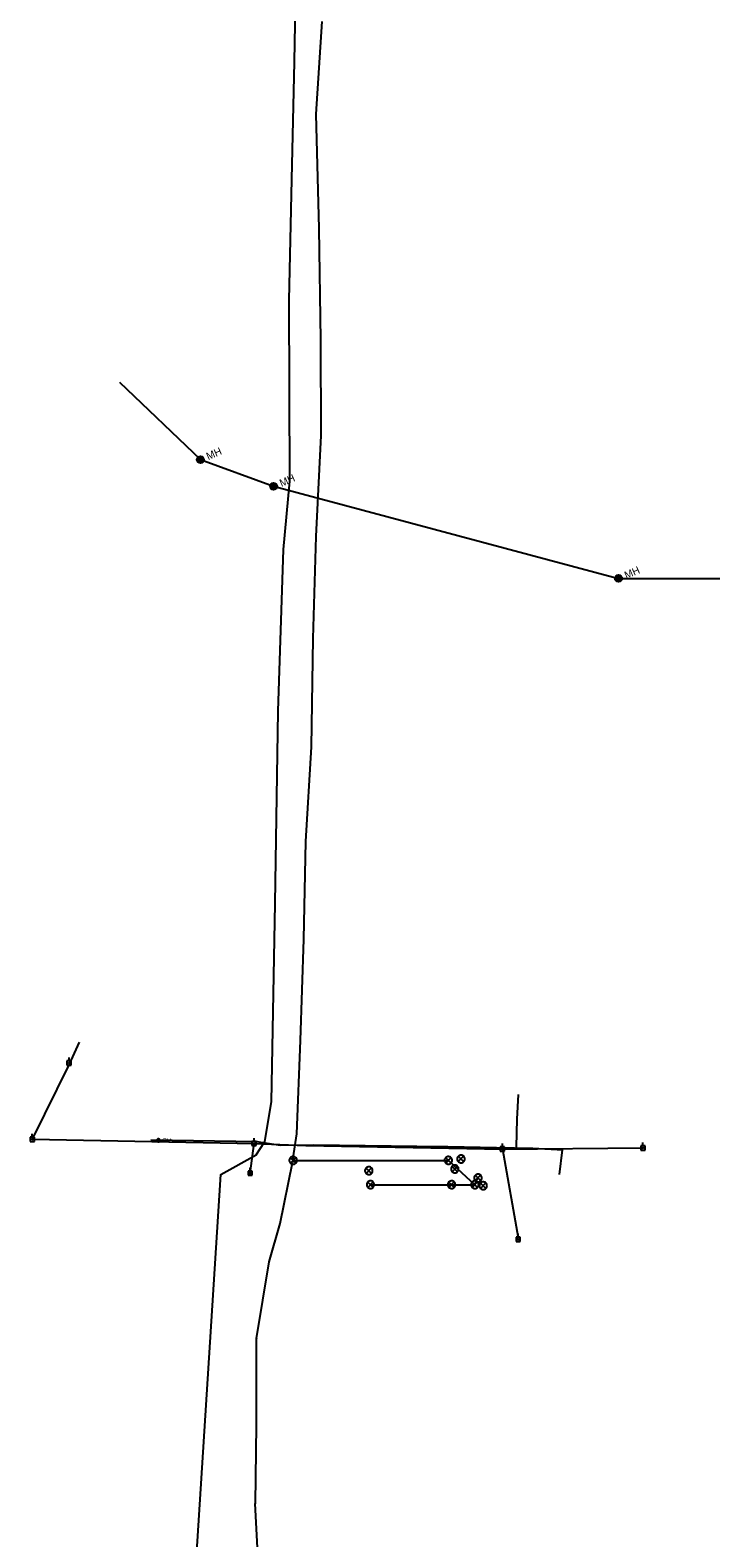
# Model space of a CAD drawing. Extents: x 600849 to 606371, y 330010 to 403088.
# Drawn here: x 603935 to 604530, y 341634 to 342935 of the extents above; entities that cross this region are included whole.
import ezdxf

# ---------------------------------------------------------------- set-up
doc = ezdxf.new("R2010")
doc.units = 0
for name, color, linetype in [('E_FTMS', 7, 'Continuous'), ('E_FTMS_Conduit', 7, 'Continuous'), ('E_UTL_EPowerPole', 7, 'Continuous'), ('E_UTL_FO_UG_QWEST', 7, 'Continuous'), ('E_UTL_G', 7, 'Continuous'), ('E_UTL_G_UG', 7, 'Continuous'), ('E_UTL_Overhead', 7, 'Continuous'), ('E_UTL_SAN_MH', 7, 'Continuous'), ('E_UTL_SAN_UG', 7, 'Continuous')]:
    doc.layers.add(name, color=color, linetype=linetype)

msp = doc.modelspace()

# ---------------------------------------------------------------- linework, layer by layer
at = {"layer": 'E_FTMS'}
for points in [[(604165.1, 341959.5), (604165.1, 341960.2), (604164.9, 341960.8), (604164.6, 341961.3), (604164.2, 341961.8), (604163.7, 341962.2), (604163.2, 341962.5), (604162.6, 341962.7), (604162, 341962.8), (604161.3, 341962.8), (604160.7, 341962.7), (604160.2, 341962.4), (604159.7, 341962), (604159.2, 341961.6), (604158.9, 341961), (604158.6, 341960.5), (604158.5, 341959.8), (604158.5, 341959.2), (604158.6, 341958.6), (604158.9, 341958), (604159.2, 341957.5), (604159.7, 341957), (604160.2, 341956.7), (604160.7, 341956.4), (604161.3, 341956.3), (604162, 341956.2), (604162.6, 341956.3), (604163.2, 341956.5), (604163.7, 341956.8), (604164.2, 341957.3), (604164.6, 341957.8), (604164.9, 341958.3), (604165.1, 341958.9), (604165.1, 341959.5)], [(604164.1, 341961.9), (604159.5, 341957.2)], [(604159.5, 341961.8), (604164.1, 341957.2)], [(604299.1, 341959.5), (604299, 341960.2), (604298.9, 341960.8), (604298.6, 341961.3), (604298.2, 341961.8), (604297.7, 341962.2), (604297.2, 341962.5), (604296.6, 341962.7), (604296, 341962.8), (604295.3, 341962.8), (604294.7, 341962.7), (604294.2, 341962.4), (604293.6, 341962), (604293.2, 341961.6), (604292.9, 341961), (604292.6, 341960.5), (604292.5, 341959.8), (604292.5, 341959.2), (604292.6, 341958.6), (604292.9, 341958), (604293.2, 341957.5), (604293.6, 341957), (604294.2, 341956.7), (604294.7, 341956.4), (604295.3, 341956.3), (604296, 341956.2), (604296.6, 341956.3), (604297.2, 341956.5), (604297.7, 341956.8), (604298.2, 341957.3), (604298.6, 341957.8), (604298.9, 341958.3), (604299, 341958.9), (604299.1, 341959.5)], [(604298.1, 341961.9), (604293.5, 341957.2)], [(604293.5, 341961.8), (604298.1, 341957.2)], [(604304.6, 341952), (604304.6, 341952.7), (604304.4, 341953.3), (604304.1, 341953.8), (604303.7, 341954.3), (604303.3, 341954.7), (604302.7, 341955), (604302.1, 341955.3), (604301.5, 341955.3), (604300.9, 341955.3), (604300.3, 341955.2), (604299.7, 341954.9), (604299.2, 341954.5), (604298.8, 341954.1), (604298.4, 341953.6), (604298.2, 341953), (604298.1, 341952.4), (604298.1, 341951.7), (604298.2, 341951.1), (604298.4, 341950.5), (604298.8, 341950), (604299.2, 341949.6), (604299.7, 341949.2), (604300.3, 341948.9), (604300.9, 341948.8), (604301.5, 341948.8), (604302.1, 341948.8), (604302.7, 341949), (604303.3, 341949.4), (604303.7, 341949.8), (604304.1, 341950.3), (604304.4, 341950.8), (604304.6, 341951.4), (604304.6, 341952)], [(604310, 341960.7), (604309.9, 341961.3), (604309.7, 341961.9), (604309.5, 341962.5), (604309.1, 341963), (604308.6, 341963.4), (604308, 341963.7), (604307.5, 341963.9), (604306.8, 341964), (604306.2, 341964), (604305.6, 341963.8), (604305, 341963.6), (604304.5, 341963.2), (604304.1, 341962.7), (604303.7, 341962.2), (604303.5, 341961.6), (604303.4, 341961), (604303.4, 341960.4), (604303.5, 341959.8), (604303.7, 341959.2), (604304.1, 341958.7), (604304.5, 341958.2), (604305, 341957.9), (604305.6, 341957.6), (604306.2, 341957.4), (604306.8, 341957.4), (604307.5, 341957.5), (604308, 341957.7), (604308.6, 341958), (604309.1, 341958.4), (604309.5, 341958.9), (604309.7, 341959.5), (604309.9, 341960.1), (604310, 341960.7)], [(604308.9, 341963), (604304.3, 341958.4)], [(604304.3, 341963), (604309, 341958.3)], [(604230.4, 341950.6), (604230.4, 341951.2), (604230.2, 341951.8), (604229.9, 341952.4), (604229.5, 341952.9), (604229, 341953.3), (604228.5, 341953.6), (604227.9, 341953.8), (604227.3, 341953.9), (604226.6, 341953.9), (604226, 341953.7), (604225.5, 341953.5), (604225, 341953.1), (604224.5, 341952.7), (604224.2, 341952.1), (604223.9, 341951.6), (604223.8, 341950.9), (604223.8, 341950.3), (604223.9, 341949.7), (604224.2, 341949.1), (604224.5, 341948.6), (604225, 341948.1), (604225.5, 341947.8), (604226, 341947.5), (604226.6, 341947.4), (604227.3, 341947.3), (604227.9, 341947.4), (604228.5, 341947.6), (604229, 341947.9), (604229.5, 341948.3), (604229.9, 341948.8), (604230.2, 341949.4), (604230.4, 341950), (604230.4, 341950.6)], [(604229.4, 341953), (604224.8, 341948.3)], [(604224.8, 341952.9), (604229.4, 341948.3)], [(604303.6, 341954.4), (604299, 341949.7)], [(604299, 341954.3), (604303.7, 341949.7)], [(604324.6, 341944.3), (604324.6, 341944.9), (604324.4, 341945.5), (604324.1, 341946.1), (604323.7, 341946.6), (604323.3, 341947), (604322.7, 341947.3), (604322.1, 341947.5), (604321.5, 341947.6), (604320.9, 341947.6), (604320.3, 341947.4), (604319.7, 341947.2), (604319.2, 341946.8), (604318.8, 341946.3), (604318.4, 341945.8), (604318.2, 341945.2), (604318.1, 341944.6), (604318.1, 341944), (604318.2, 341943.4), (604318.4, 341942.8), (604318.8, 341942.3), (604319.2, 341941.8), (604319.7, 341941.4), (604320.3, 341941.2), (604320.9, 341941), (604321.5, 341941), (604322.1, 341941.1), (604322.7, 341941.3), (604323.3, 341941.6), (604323.7, 341942), (604324.1, 341942.5), (604324.4, 341943.1), (604324.6, 341943.7), (604324.6, 341944.3)], [(604323.6, 341946.6), (604319, 341942)], [(604319, 341946.6), (604323.7, 341941.9)], [(604231.9, 341938.5), (604231.8, 341939.2), (604231.6, 341939.8), (604231.3, 341940.3), (604231, 341940.8), (604230.5, 341941.2), (604229.9, 341941.5), (604229.3, 341941.7), (604228.7, 341941.8), (604228.1, 341941.8), (604227.5, 341941.6), (604226.9, 341941.4), (604226.4, 341941), (604226, 341940.6), (604225.6, 341940), (604225.4, 341939.5), (604225.3, 341938.8), (604225.3, 341938.2), (604225.4, 341937.6), (604225.6, 341937), (604226, 341936.5), (604226.4, 341936), (604226.9, 341935.7), (604227.5, 341935.4), (604228.1, 341935.3), (604228.7, 341935.2), (604229.3, 341935.3), (604229.9, 341935.5), (604230.5, 341935.8), (604231, 341936.3), (604231.3, 341936.7), (604231.6, 341937.3), (604231.8, 341937.9), (604231.9, 341938.5)], [(604230.8, 341940.9), (604226.2, 341936.2)], [(604226.2, 341940.8), (604230.9, 341936.2)], [(604301.9, 341938.5), (604301.8, 341939.2), (604301.6, 341939.8), (604301.4, 341940.3), (604301, 341940.8), (604300.5, 341941.2), (604300, 341941.5), (604299.4, 341941.7), (604298.7, 341941.8), (604298.1, 341941.8), (604297.5, 341941.6), (604296.9, 341941.4), (604296.4, 341941), (604296, 341940.6), (604295.7, 341940), (604295.4, 341939.5), (604295.3, 341938.8), (604295.3, 341938.2), (604295.4, 341937.6), (604295.7, 341937), (604296, 341936.5), (604296.4, 341936), (604296.9, 341935.7), (604297.5, 341935.4), (604298.1, 341935.3), (604298.7, 341935.2), (604299.4, 341935.3), (604300, 341935.5), (604300.5, 341935.8), (604301, 341936.3), (604301.4, 341936.7), (604301.6, 341937.3), (604301.8, 341937.9), (604301.9, 341938.5)], [(604300.8, 341940.9), (604296.2, 341936.2)], [(604296.2, 341940.8), (604300.9, 341936.2)], [(604322, 341938.5), (604321.9, 341939.2), (604321.8, 341939.8), (604321.5, 341940.3), (604321.1, 341940.8), (604320.6, 341941.2), (604320.1, 341941.5), (604319.5, 341941.7), (604318.9, 341941.8), (604318.2, 341941.8), (604317.6, 341941.6), (604317.1, 341941.4), (604316.5, 341941), (604316.1, 341940.6), (604315.8, 341940), (604315.5, 341939.5), (604315.4, 341938.8), (604315.4, 341938.2), (604315.5, 341937.6), (604315.8, 341937), (604316.1, 341936.5), (604316.5, 341936), (604317.1, 341935.7), (604317.6, 341935.4), (604318.2, 341935.3), (604318.9, 341935.2), (604319.5, 341935.3), (604320.1, 341935.5), (604320.6, 341935.8), (604321.1, 341936.3), (604321.5, 341936.7), (604321.8, 341937.3), (604321.9, 341937.9), (604322, 341938.5)], [(604321, 341940.9), (604316.4, 341936.2)], [(604316.4, 341940.8), (604321, 341936.2)], [(604329.2, 341937.6), (604329.1, 341938.3), (604329, 341938.9), (604328.7, 341939.4), (604328.3, 341939.9), (604327.8, 341940.3), (604327.3, 341940.6), (604326.7, 341940.8), (604326.1, 341940.9), (604325.4, 341940.9), (604324.8, 341940.8), (604324.3, 341940.5), (604323.7, 341940.1), (604323.3, 341939.7), (604323, 341939.2), (604322.7, 341938.6), (604322.6, 341938), (604322.6, 341937.3), (604322.7, 341936.7), (604323, 341936.1), (604323.3, 341935.6), (604323.7, 341935.1), (604324.3, 341934.8), (604324.8, 341934.5), (604325.4, 341934.4), (604326.1, 341934.3), (604326.7, 341934.4), (604327.3, 341934.6), (604327.8, 341935), (604328.3, 341935.4), (604328.7, 341935.9), (604329, 341936.4), (604329.1, 341937), (604329.2, 341937.6)], [(604328.2, 341940), (604323.6, 341935.3)], [(604323.6, 341939.9), (604328.2, 341935.3)]]:
    msp.add_lwpolyline(points, dxfattribs=at)
at = {"layer": 'E_FTMS_Conduit'}
for points in [[(604131.7, 341614.1), (604129.2, 341663.2), (604129.3, 341663.2), (604130.1, 341731), (604130.3, 341805.8), (604130.3, 341805.9), (604130.3, 341805.8), (604130.3, 341805.8), (604141.1, 341871.9), (604150.5, 341905), (604161.4, 341957.5), (604161.8, 341959.5), (604161.9, 341961.6), (604164.9, 341982.3), (604168.1, 342063.1), (604171.1, 342150.5), (604172.7, 342234.8), (604177.7, 342316.6), (604179.2, 342410), (604181.8, 342498), (604185.9, 342585.2), (604185.8, 342667.9), (604184.3, 342763.9), (604181.6, 342862.8), (604187, 342942.7)], [(604161.8, 341959.5), (604295.8, 341959.5), (604318.7, 341938.5)], [(604228.6, 341938.5), (604298.6, 341938.5), (604318.7, 341938.5), (604321.3, 341944.3)]]:
    msp.add_lwpolyline(points, dxfattribs=at)
at = {"layer": 'E_UTL_EPowerPole'}
for points in [[(603968.5, 342045.3), (603968.5, 342048.2)], [(603970.3, 342045.3), (603966.6, 342045.3)], [(603966.6, 342045.3), (603966.6, 342041.6)], [(603966.6, 342041.6), (603970.3, 342041.6)], [(603968.7, 342043.5), (603968.7, 342043.5), (603968.7, 342043.6), (603968.7, 342043.6), (603968.7, 342043.6), (603968.6, 342043.7), (603968.6, 342043.7), (603968.6, 342043.7), (603968.5, 342043.7), (603968.5, 342043.7), (603968.4, 342043.7), (603968.4, 342043.7), (603968.4, 342043.7), (603968.3, 342043.6), (603968.3, 342043.6), (603968.3, 342043.6), (603968.3, 342043.5), (603968.3, 342043.5), (603968.3, 342043.4), (603968.3, 342043.4), (603968.3, 342043.3), (603968.4, 342043.3), (603968.4, 342043.3), (603968.4, 342043.3), (603968.5, 342043.2), (603968.5, 342043.2), (603968.6, 342043.3), (603968.6, 342043.3), (603968.6, 342043.3), (603968.7, 342043.3), (603968.7, 342043.4), (603968.7, 342043.4), (603968.7, 342043.4), (603968.7, 342043.5)], [(603970.3, 342041.6), (603970.3, 342045.3)], [(603936.7, 341979.6), (603936.7, 341982.5)], [(603938.6, 341979.6), (603934.9, 341979.6)], [(603934.9, 341979.6), (603934.9, 341975.9)], [(603934.9, 341975.9), (603938.6, 341975.9)], [(603937, 341977.8), (603937, 341977.8), (603937, 341977.9), (603937, 341977.9), (603936.9, 341978), (603936.9, 341978), (603936.9, 341978), (603936.8, 341978), (603936.8, 341978), (603936.7, 341978), (603936.7, 341978), (603936.6, 341978), (603936.6, 341978), (603936.6, 341977.9), (603936.6, 341977.9), (603936.5, 341977.9), (603936.5, 341977.8), (603936.5, 341977.8), (603936.5, 341977.7), (603936.6, 341977.7), (603936.6, 341977.6), (603936.6, 341977.6), (603936.6, 341977.6), (603936.7, 341977.6), (603936.7, 341977.6), (603936.8, 341977.6), (603936.8, 341977.6), (603936.9, 341977.6), (603936.9, 341977.6), (603936.9, 341977.6), (603937, 341977.7), (603937, 341977.7), (603937, 341977.7), (603937, 341977.8)], [(603938.6, 341975.9), (603938.6, 341979.6)], [(604130, 341975.9), (604126.3, 341975.9)], [(604126.3, 341975.9), (604126.3, 341972.2)], [(604126.3, 341972.2), (604130, 341972.2)], [(604128.4, 341974.1), (604128.4, 341974.1), (604128.4, 341974.2), (604128.4, 341974.2), (604128.4, 341974.2), (604128.3, 341974.3), (604128.3, 341974.3), (604128.2, 341974.3), (604128.2, 341974.3), (604128.1, 341974.3), (604128.1, 341974.3), (604128.1, 341974.3), (604128, 341974.2), (604128, 341974.2), (604128, 341974.2), (604128, 341974.1), (604127.9, 341974.1), (604127.9, 341974), (604128, 341974), (604128, 341974), (604128, 341973.9), (604128, 341973.9), (604128.1, 341973.9), (604128.1, 341973.8), (604128.1, 341973.8), (604128.2, 341973.8), (604128.2, 341973.8), (604128.3, 341973.9), (604128.3, 341973.9), (604128.4, 341973.9), (604128.4, 341973.9), (604128.4, 341974), (604128.4, 341974), (604128.4, 341974.1)], [(604128.1, 341975.9), (604128.1, 341978.8)], [(604130, 341972.2), (604130, 341975.9)], [(604344.2, 341971.2), (604340.6, 341971.2)], [(604340.6, 341971.2), (604340.6, 341967.5)], [(604342.7, 341969.3), (604342.7, 341969.4), (604342.7, 341969.4), (604342.6, 341969.5), (604342.6, 341969.5), (604342.6, 341969.5), (604342.5, 341969.6), (604342.5, 341969.6), (604342.4, 341969.6), (604342.4, 341969.6), (604342.4, 341969.6), (604342.3, 341969.6), (604342.3, 341969.5), (604342.2, 341969.5), (604342.2, 341969.5), (604342.2, 341969.4), (604342.2, 341969.4), (604342.2, 341969.3), (604342.2, 341969.3), (604342.2, 341969.2), (604342.2, 341969.2), (604342.3, 341969.2), (604342.3, 341969.1), (604342.4, 341969.1), (604342.4, 341969.1), (604342.4, 341969.1), (604342.5, 341969.1), (604342.5, 341969.1), (604342.6, 341969.2), (604342.6, 341969.2), (604342.6, 341969.2), (604342.7, 341969.3), (604342.7, 341969.3), (604342.7, 341969.3)], [(604342.4, 341971.2), (604342.4, 341974.1)], [(604344.2, 341967.5), (604344.2, 341971.2)], [(604465.5, 341972.1), (604461.8, 341972.1)], [(604461.8, 341972.1), (604461.8, 341968.4)], [(604461.8, 341968.4), (604465.5, 341968.4)], [(604463.9, 341970.2), (604463.9, 341970.3), (604463.9, 341970.3), (604463.9, 341970.4), (604463.8, 341970.4), (604463.8, 341970.4), (604463.8, 341970.5), (604463.7, 341970.5), (604463.7, 341970.5), (604463.6, 341970.5), (604463.6, 341970.5), (604463.5, 341970.5), (604463.5, 341970.4), (604463.5, 341970.4), (604463.4, 341970.4), (604463.4, 341970.3), (604463.4, 341970.3), (604463.4, 341970.2), (604463.4, 341970.2), (604463.4, 341970.1), (604463.5, 341970.1), (604463.5, 341970.1), (604463.5, 341970), (604463.6, 341970), (604463.6, 341970), (604463.7, 341970), (604463.7, 341970), (604463.8, 341970), (604463.8, 341970), (604463.8, 341970.1), (604463.9, 341970.1), (604463.9, 341970.2), (604463.9, 341970.2), (604463.9, 341970.2)], [(604463.6, 341972.1), (604463.6, 341975)], [(604465.5, 341968.4), (604465.5, 341972.1)], [(604340.6, 341967.5), (604344.2, 341967.5)], [(604126.6, 341950.2), (604122.9, 341950.2)], [(604122.9, 341950.2), (604122.9, 341946.6)], [(604122.9, 341946.6), (604126.6, 341946.6)], [(604125, 341948.4), (604125, 341948.4), (604125, 341948.5), (604125, 341948.5), (604125, 341948.6), (604124.9, 341948.6), (604124.9, 341948.6), (604124.8, 341948.6), (604124.8, 341948.6), (604124.7, 341948.6), (604124.7, 341948.6), (604124.7, 341948.6), (604124.6, 341948.6), (604124.6, 341948.6), (604124.6, 341948.5), (604124.6, 341948.5), (604124.5, 341948.4), (604124.5, 341948.4), (604124.6, 341948.3), (604124.6, 341948.3), (604124.6, 341948.3), (604124.6, 341948.2), (604124.7, 341948.2), (604124.7, 341948.2), (604124.7, 341948.2), (604124.8, 341948.2), (604124.8, 341948.2), (604124.9, 341948.2), (604124.9, 341948.2), (604125, 341948.2), (604125, 341948.3), (604125, 341948.3), (604125, 341948.4), (604125, 341948.4)], [(604124.7, 341950.2), (604124.7, 341953.2)], [(604126.6, 341946.6), (604126.6, 341950.2)], [(604357.9, 341893.2), (604354.2, 341893.2)], [(604354.2, 341893.2), (604354.2, 341889.5)], [(604356.3, 341891.4), (604356.3, 341891.4), (604356.3, 341891.5), (604356.2, 341891.5), (604356.2, 341891.6), (604356.2, 341891.6), (604356.1, 341891.6), (604356.1, 341891.6), (604356.1, 341891.6), (604356, 341891.6), (604356, 341891.6), (604355.9, 341891.6), (604355.9, 341891.6), (604355.9, 341891.5), (604355.8, 341891.5), (604355.8, 341891.5), (604355.8, 341891.4), (604355.8, 341891.4), (604355.8, 341891.3), (604355.8, 341891.3), (604355.9, 341891.2), (604355.9, 341891.2), (604355.9, 341891.2), (604356, 341891.2), (604356, 341891.2), (604356.1, 341891.2), (604356.1, 341891.2), (604356.1, 341891.2), (604356.2, 341891.2), (604356.2, 341891.2), (604356.2, 341891.3), (604356.3, 341891.3), (604356.3, 341891.3), (604356.3, 341891.4)], [(604356, 341893.2), (604356, 341896.1)], [(604357.9, 341889.5), (604357.9, 341893.2)], [(604354.2, 341889.5), (604357.9, 341889.5)]]:
    msp.add_lwpolyline(points, dxfattribs=at)
at = {"layer": 'E_UTL_FO_UG_QWEST'}
msp.add_lwpolyline([(604106.1, 340314.8), (604109.8, 340459.7), (604113, 340550.1), (604126.5, 340666.8), (604128, 340788.1), (604132.1, 341165.4), (604131.3, 341174.9), (604074, 341549.3), (604099.4, 341947.2), (604129.9, 341964.3), (604137.3, 341975.9), (604143.1, 342010), (604146.2, 342181.2), (604149, 342347.4), (604153.5, 342486.9), (604159.1, 342545.7), (604158.4, 342702.2), (604160.7, 342806.3), (604162.9, 342907.9), (604165.4, 343038.3)], dxfattribs=at)
at = {"layer": 'E_UTL_G'}
for points in [[(604046.8, 341976.8), (604046.8, 341977), (604046.8, 341977.2), (604046.6, 341977.5), (604046.5, 341977.7), (604046.3, 341977.8), (604046.1, 341977.9), (604045.9, 341978), (604045.6, 341978), (604045.4, 341978), (604045.1, 341978), (604044.9, 341977.9), (604044.7, 341977.7), (604044.6, 341977.6), (604044.4, 341977.4), (604044.3, 341977.1), (604044.3, 341976.9), (604044.3, 341976.6), (604044.3, 341976.4), (604044.4, 341976.2), (604044.6, 341976), (604044.7, 341975.8), (604044.9, 341975.7), (604045.1, 341975.6), (604045.4, 341975.5), (604045.6, 341975.5), (604045.9, 341975.5), (604046.1, 341975.6), (604046.3, 341975.7), (604046.5, 341975.9), (604046.6, 341976.1), (604046.8, 341976.3), (604046.8, 341976.5), (604046.8, 341976.8)], [(604044.7, 341975.9), (604046.5, 341977.7)]]:
    msp.add_lwpolyline(points, dxfattribs=at)
at = {"layer": 'E_UTL_G_UG'}
for points in [[(604355.9, 342016.5), (604354.9, 341995.2), (604354.2, 341971.2), (604354.2, 341970.1)], [(604039.1, 341977.3), (604130.7, 341975.7), (604133.8, 341975.2)], [(604133.8, 341975.2), (604150.9, 341972.5), (604179.5, 341973), (604291.1, 341971.5), (604295.4, 341971.5), (604337.2, 341970.5), (604368.8, 341969.9), (604395, 341968.6)], [(604394.1, 341968.7), (604391.5, 341947.2)]]:
    msp.add_lwpolyline(points, dxfattribs=at)
at = {"layer": 'E_UTL_Overhead'}
for points in [[(603936.8, 341977.8), (603968.8, 342042.5), (603977.5, 342061.6)], [(603936.8, 341977.8), (604128.2, 341974.1), (604172.9, 341972.2), (604342.4, 341969.3)], [(604124.8, 341948.4), (604128.2, 341974.1)], [(604342.4, 341969.3), (604463.7, 341970.2)], [(604342.4, 341969.3), (604356, 341892.5)]]:
    msp.add_lwpolyline(points, dxfattribs=at)
at = {"layer": 'E_UTL_SAN_MH'}
for centre, radius in [((604081.8, 342564.4), 3), ((604081.8, 342564.4), 2.4), ((604081.8, 342564.4), 0.9), ((604145, 342541.4), 3), ((604145, 342541.4), 2.4), ((604145, 342541.4), 0.9), ((604442.6, 342461.9), 3), ((604442.6, 342461.9), 2.4), ((604442.6, 342461.9), 0.9)]:
    msp.add_circle(centre, radius, dxfattribs=at)
at = {"layer": 'E_UTL_SAN_UG'}
for p, q in [((604012, 342631.4), (604081.8, 342564.4)), ((604442.6, 342461.9), (604530.1, 342461.9))]:
    msp.add_line(p, q, dxfattribs=at)
for points in [[(604081.8, 342564.4), (604145, 342541.4)], [(604145, 342541.4), (604442.6, 342461.9)]]:
    msp.add_lwpolyline(points, dxfattribs=at)

# ---------------------------------------------------------------- texts
at = {"layer": 'E_UTL_G'}
msp.add_text('GV', height=3.85, dxfattribs=at).set_placement((604048.8, 341974.8))
at = {"layer": 'E_UTL_SAN_MH'}
for p in [(604088.6, 342563.9), (604151.8, 342540.8), (604449.4, 342461.3)]:
    msp.add_text('MH', height=6.48, rotation=23.5436, dxfattribs=at).set_placement(p)

doc.saveas('drawing.dxf')
